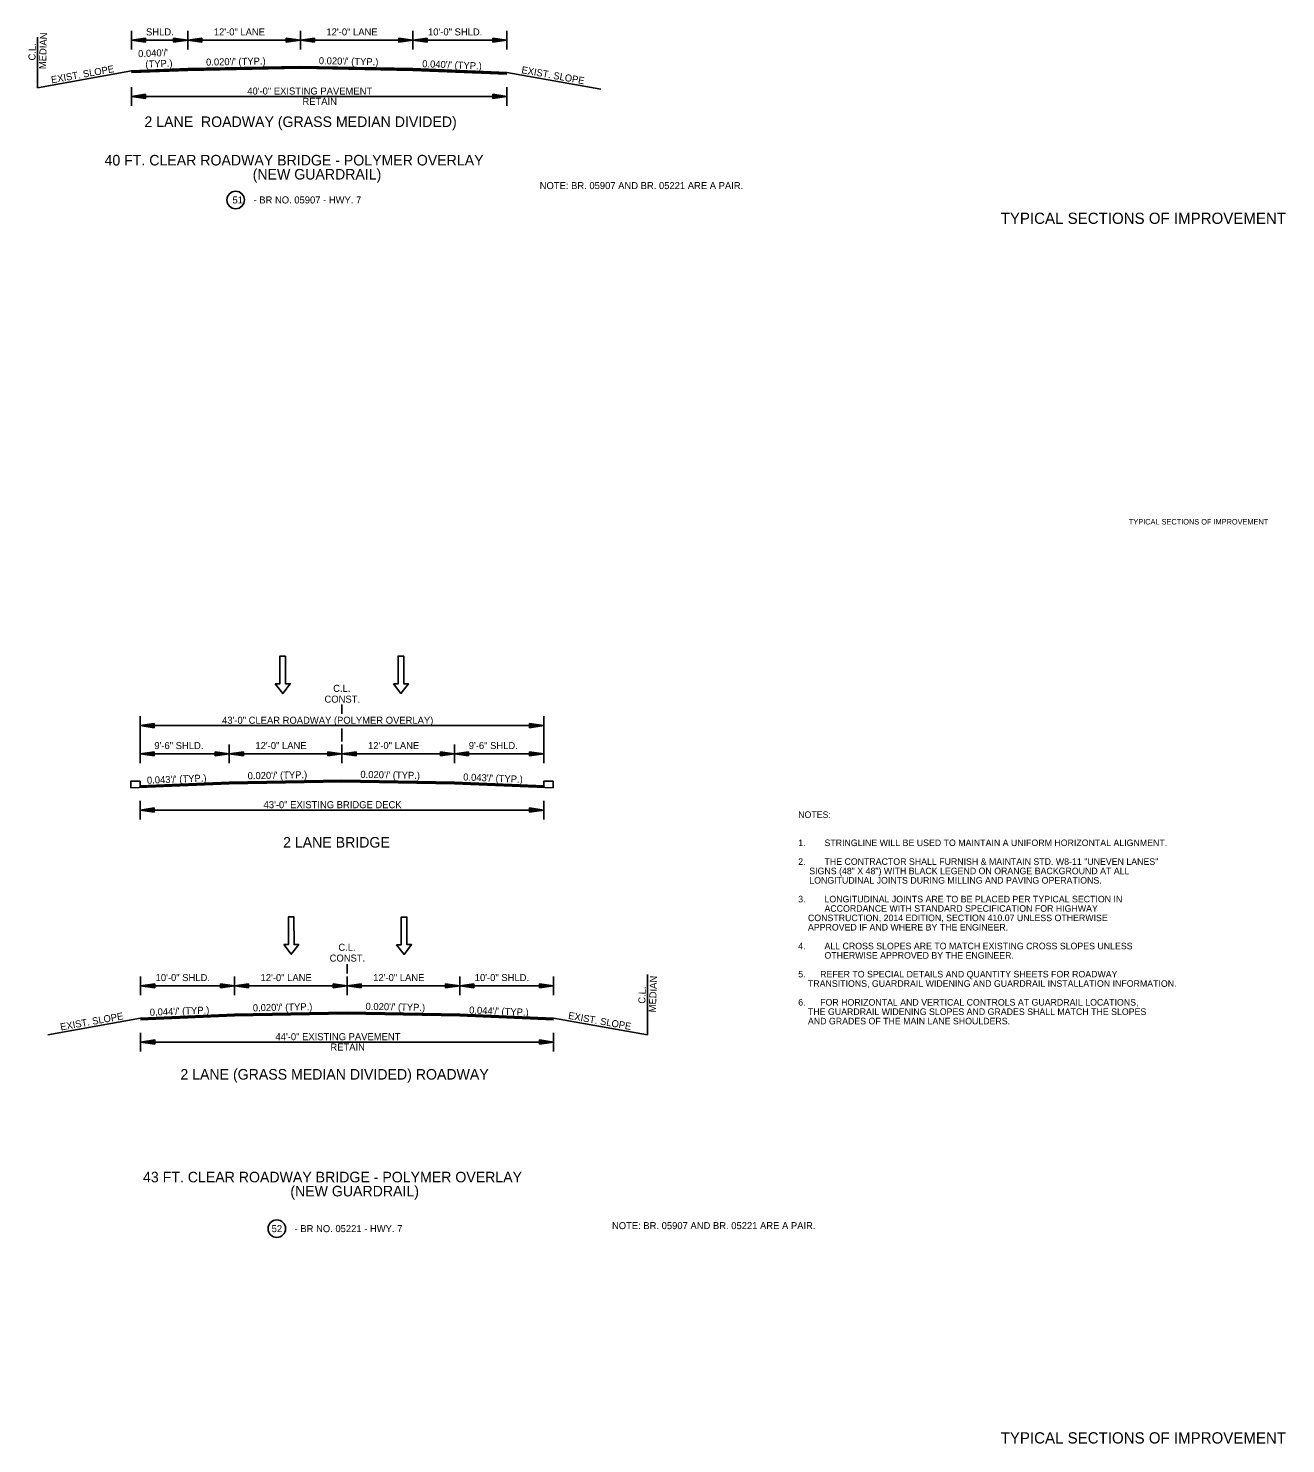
# Model space of a CAD drawing. Extents: x 545241 to 1930787, y -1971772 to 596640.
# Drawn here: x 546928 to 548268, y -1971772 to -1970263 of the extents above; entities that cross this region are included whole.
import ezdxf

# ---------------------------------------------------------------- set-up
doc = ezdxf.new("R2010")
doc.units = 0
for name, color, linetype in [('R_Border', 7, 'Continuous'), ('R_Border Notes', 7, 'Continuous'), ('R_Border Prem', 7, 'Continuous'), ('R_Draft', 7, 'Continuous')]:
    doc.layers.add(name, color=color, linetype=linetype)

# ---------------------------------------------------------------- blocks, each defined once
blk = doc.blocks.new('ARROW')
at = {"layer": 'R_Draft'}
for p, q in [((-2, 0.3), (0, 0)), ((-2, 0.3), (-2, -0.3)), ((-2, 0.25), (-0.334, 0)), ((-2, 0.199), (-0.678, 0)), ((-2, 0.149), (-1.011, 0)), ((-2, 0.097), (-1.35, 0)), ((-2, 0.047), (-1.684, 0)), ((-2, -0.3), (0, 0)), ((-2, -0.098), (-1.35, 0)), ((-2, -0.199), (-0.678, 0)), ((-2, -0.25), (-0.334, 0)), ((-2, -0.149), (-1.011, 0)), ((-2, -0.047), (-1.684, 0))]:
    blk.add_line(p, q, dxfattribs=at)
blk = doc.blocks.new('BPPOLY')
at = {"layer": 'R_Border'}
blk.add_circle((0, 0), 9.34, dxfattribs=at)

msp = doc.modelspace()

# ---------------------------------------------------------------- linework, layer by layer
at = {"layer": 'R_Border'}
for p, q in [((547038.1, -1970265.7), (547038.1, -1970285.7)), ((547098.1, -1970265.7), (547098.1, -1970285.7)), ((547218.1, -1970265.7), (547218.1, -1970285.7)), ((547338.1, -1970265.7), (547338.1, -1970285.7)), ((547438.1, -1970265.7), (547438.1, -1970285.7)), ((546938.2, -1970272.4), (546938.2, -1970326.7)), ((547038.1, -1970275.7), (547438.1, -1970275.7)), ((547038.1, -1970308.5), (546938.2, -1970326.7)), ((547438.1, -1970310.1), (547538.1, -1970328.1)), ((547038.1, -1970325.7), (547038.1, -1970345.7)), ((547438.1, -1970325.7), (547438.1, -1970345.7)), ((547038.1, -1970335.7), (547438.1, -1970335.7)), ((547262.4, -1970983.9), (547262.4, -1970993.9)), ((547047.4, -1970996.4), (547047.4, -1971046.4)), ((547047.4, -1971006.4), (547477.4, -1971006.4)), ((547262.4, -1971009.4), (547262.4, -1971023.4)), ((547477.4, -1970996.4), (547477.4, -1971046.4)), ((547047.4, -1971036.4), (547477.4, -1971036.4)), ((547142.4, -1971026.4), (547142.4, -1971046.4)), ((547262.4, -1971026.4), (547262.4, -1971046.4)), ((547382.4, -1971026.4), (547382.4, -1971046.4)), ((547047.4, -1971086.4), (547047.4, -1971106.4)), ((547047.4, -1971096.4), (547477.4, -1971096.4)), ((547477.4, -1971086.4), (547477.4, -1971106.4)), ((547267.9, -1971260.7), (547267.9, -1971270.7)), ((547047.9, -1971273.7), (547047.9, -1971293.7)), ((547147.9, -1971273.7), (547147.9, -1971293.7)), ((547267.9, -1971273.7), (547267.9, -1971293.7)), ((547387.9, -1971273.7), (547387.9, -1971293.7)), ((547487.9, -1971273.7), (547487.9, -1971293.7)), ((547587.9, -1971271.8), (547587.9, -1971336.1)), ((547047.9, -1971283.7), (547487.9, -1971283.7)), ((547047.9, -1971318.1), (546949.2, -1971336.1)), ((547487.9, -1971318.1), (547587.9, -1971336.1)), ((547047.9, -1971333.7), (547047.9, -1971353.7)), ((547487.9, -1971333.7), (547487.9, -1971353.7)), ((547047.9, -1971343.7), (547487.9, -1971343.7))]:
    msp.add_line(p, q, dxfattribs=at)
for points in [[(547038.1, -1970308.5), (547098.1, -1970306.1), (547218.1, -1970303.7), (547338.1, -1970306.1), (547438.1, -1970310.1)], [(547038.1, -1970308.8), (547098.1, -1970306.4), (547218.1, -1970304), (547338.1, -1970306.4), (547438.1, -1970310.4)], [(547038.1, -1970309.1), (547098.1, -1970306.7), (547218.1, -1970304.3), (547338.1, -1970306.7), (547438.1, -1970310.7)], [(547038.1, -1970309.4), (547098.1, -1970307), (547218.1, -1970304.6), (547338.1, -1970307), (547438.1, -1970311)], [(547038.1, -1970309.7), (547098.1, -1970307.3), (547218.1, -1970304.9), (547338.1, -1970307.3), (547438.1, -1970311.3)], [(547038.1, -1970310), (547098.1, -1970307.6), (547218.1, -1970305.2), (547338.1, -1970307.6), (547438.1, -1970311.6)], [(547038.1, -1970310.3), (547098.1, -1970307.9), (547218.1, -1970305.5), (547338.1, -1970307.9), (547438.1, -1970311.9)], [(547047.4, -1971072.1), (547047.4, -1971065.6), (547037.4, -1971065.6), (547037.4, -1971072.8)], [(547037.4, -1971072.8), (547142.4, -1971068.6), (547262.4, -1971066.2), (547382.4, -1971068.6), (547487.4, -1971072.8)], [(547047.4, -1971070.6), (547142.4, -1971066.8), (547262.4, -1971064.4), (547382.4, -1971066.8), (547477.4, -1971070.6)], [(547047.4, -1971070.9), (547142.4, -1971067.1), (547262.4, -1971064.7), (547382.4, -1971067.1), (547477.4, -1971070.9)], [(547047.4, -1971071.2), (547142.4, -1971067.4), (547262.4, -1971065), (547382.4, -1971067.4), (547477.4, -1971071.2)], [(547047.4, -1971071.5), (547142.4, -1971067.7), (547262.4, -1971065.3), (547382.4, -1971067.7), (547477.4, -1971071.5)], [(547047.4, -1971071.8), (547142.4, -1971068), (547262.4, -1971065.6), (547382.4, -1971068), (547477.4, -1971071.8)], [(547047.4, -1971072.1), (547142.4, -1971068.3), (547262.4, -1971065.9), (547382.4, -1971068.3), (547477.4, -1971072.1)], [(547477.4, -1971072.1), (547477.4, -1971065.6), (547487.4, -1971065.6), (547487.4, -1971072.8)], [(547047.9, -1971318.1), (547147.9, -1971314.1), (547267.9, -1971311.7), (547387.9, -1971314.1), (547487.9, -1971318.1)], [(547047.9, -1971318.4), (547147.9, -1971314.4), (547267.9, -1971312), (547387.9, -1971314.4), (547487.9, -1971318.4)], [(547047.9, -1971318.7), (547147.9, -1971314.7), (547267.9, -1971312.3), (547387.9, -1971314.7), (547487.9, -1971318.7)], [(547047.9, -1971319), (547147.9, -1971315), (547267.9, -1971312.6), (547387.9, -1971315), (547487.9, -1971319)], [(547047.9, -1971319.3), (547147.9, -1971315.3), (547267.9, -1971312.9), (547387.9, -1971315.3), (547487.9, -1971319.3)], [(547047.9, -1971319.6), (547147.9, -1971315.6), (547267.9, -1971313.2), (547387.9, -1971315.6), (547487.9, -1971319.6)], [(547047.9, -1971319.9), (547147.9, -1971315.9), (547267.9, -1971313.5), (547387.9, -1971315.9), (547487.9, -1971319.9)]]:
    msp.add_lwpolyline(points, dxfattribs=at)
for points in [[(547191.3, -1970961.9), (547199.3, -1970972.2), (547207.3, -1970961.8), (547202.3, -1970961.8), (547202.2, -1970932.4), (547196.2, -1970932.4), (547196.3, -1970961.8)], [(547317.3, -1970961.7), (547325.3, -1970972.1), (547333.3, -1970961.7), (547328.3, -1970961.7), (547328.3, -1970932.3), (547322.3, -1970932.3), (547322.3, -1970961.7)], [(547200.4, -1971239.7), (547208.4, -1971250.1), (547216.4, -1971239.7), (547211.4, -1971239.7), (547211.3, -1971210.2), (547205.3, -1971210.3), (547205.4, -1971239.7)], [(547320.6, -1971239.9), (547328.6, -1971250.2), (547336.6, -1971239.8), (547331.6, -1971239.8), (547331.6, -1971210.4), (547325.6, -1971210.4), (547325.6, -1971239.9)]]:
    msp.add_lwpolyline(points, close=True, dxfattribs=at)

# ---------------------------------------------------------------- block references
at = {"layer": 'R_Border', "xscale": 7.5, "yscale": 7.5, "rotation": 180}
for p in [(547038.1, -1970275.7), (547098.1, -1970275.7), (547218.1, -1970275.7), (547338.1, -1970275.7), (547038.1, -1970335.7), (547047.4, -1971006.4), (547047.4, -1971036.4), (547142.4, -1971036.4), (547262.4, -1971036.4), (547382.4, -1971036.4), (547047.4, -1971096.4), (547047.9, -1971283.7), (547147.9, -1971283.7), (547267.9, -1971283.7), (547387.9, -1971283.7), (547047.9, -1971343.7)]:
    msp.add_blockref('ARROW', p, dxfattribs=at)
at = {"layer": 'R_Border', "xscale": 7.5, "yscale": 7.5}
for p in [(547098.1, -1970275.7), (547218.1, -1970275.7), (547338.1, -1970275.7), (547438.1, -1970275.7), (547438.1, -1970335.7), (547477.4, -1971006.4), (547142.4, -1971036.4), (547262.4, -1971036.4), (547382.4, -1971036.4), (547477.4, -1971036.4), (547477.4, -1971096.4), (547147.9, -1971283.7), (547267.9, -1971283.7), (547387.9, -1971283.7), (547487.9, -1971283.7), (547487.9, -1971343.7)]:
    msp.add_blockref('ARROW', p, dxfattribs=at)
at = {"layer": 'R_Border'}
for p in [(547149.2, -1970446.1), (547193, -1971542.6)]:
    msp.add_blockref('BPPOLY', p, dxfattribs=at)

# ---------------------------------------------------------------- texts
for s, height, rotation, p in [('MEDIAN', 7.5, 88.1187, (546947, -1970306.7)), ('C.L.', 7.5, 88.1187, (546935.8, -1970297.5)), ("0.040'/'", 7.5, 2.2916, (547045.4, -1970293.9)), ('(TYP.)', 7.5, 2.2916, (547053.1, -1970305.1)), ("0.020'/' (TYP.)", 7.5, 1.1458, (547117.7, -1970302.9)), ("0.020'/' (TYP.)", 7.5, 358.8542, (547237.7, -1970301.3)), ("0.040'/' (TYP.)", 7.5, 357.7084, (547347.8, -1970304.5)), ('EXIST. SLOPE', 7.5, 10.204, (546953.2, -1970321.8)), ('EXIST. SLOPE', 7.5, 349.796, (547453.2, -1970310.8)), ('TYPICAL SECTIONS OF IMPROVEMENT', 12, 360, (547964.2, -1970471.6)), ("0.020'/' (TYP.)", 7.5, 1.1458, (547162, -1971063.6)), ("0.020'/' (TYP.)", 7.5, 358.8542, (547282, -1971062)), ("0.043'/' (TYP.)", 7.5, 2.2916, (547054.8, -1971068.4)), ("0.043'/' (TYP.)", 7.5, 357.7084, (547391.5, -1971064.8)), ('MEDIAN', 7.5, 88.1187, (547596.8, -1971312.1)), ('C.L.', 7.5, 88.1187, (547585.6, -1971302.9)), ("0.044'/' (TYP.)", 7.5, 2.2916, (547057.8, -1971315.7)), ("0.020'/' (TYP.)", 7.5, 1.1458, (547167.5, -1971310.9)), ("0.020'/' (TYP.)", 7.5, 358.8542, (547287.5, -1971309.3)), ("0.044'/' (TYP.)", 7.5, 357.7084, (547397.8, -1971313.2)), ('EXIST. SLOPE', 7.5, 10.204, (546963, -1971331.4)), ('EXIST. SLOPE', 7.5, 349.796, (547503, -1971318.8)), ('TYPICAL SECTIONS OF IMPROVEMENT', 12, 360, (547964.2, -1971771.6))]:
    msp.add_text(s, height=height, rotation=rotation, dxfattribs=at).set_placement(p)
for s, height, p in [('SHLD.', 7.5, (547053.7, -1970270.7)), ('12\'-0" LANE', 7.5, (547125.9, -1970270.7)), ('12\'-0" LANE', 7.5, (547245.9, -1970270.7)), ('10\'-0" SHLD.', 7.5, (547354.1, -1970270.7)), ('40\'-0" EXISTING PAVEMENT', 7.5, (547161.5, -1970333.7)), ('RETAIN', 7.5, (547220.3, -1970344.7)), ('2 LANE  ROADWAY (GRASS MEDIAN DIVIDED)', 11.25, (547052, -1970368.3)), ('40 FT. CLEAR ROADWAY BRIDGE - POLYMER OVERLAY', 11.25, (547009.5, -1970409.3)), ('(NEW GUARDRAIL)', 11.25, (547167.3, -1970424.3)), ('NOTE: BR. 05907 AND BR. 05221 ARE A PAIR.', 7.5, (547473.1, -1970434.5)), ('51', 7.5, (547145.8, -1970449.8)), ('- BR NO. 05907 - HWY. 7', 7.5, (547168.2, -1970449.8)), ('C.L.', 7.5, (547253, -1970970.4)), ('CONST.', 7.5, (547243.8, -1970981.9)), ('43\'-0" CLEAR ROADWAY (POLYMER OVERLAY)', 7.5, (547134.7, -1971004.4)), ('9\'-6" SHLD.', 7.5, (547062.5, -1971031.4)), ('12\'-0" LANE', 7.5, (547170.2, -1971031.4)), ('12\'-0" LANE', 7.5, (547290.2, -1971031.4)), ('9\'-6" SHLD.', 7.5, (547397.5, -1971031.4)), ('43\'-0" EXISTING BRIDGE DECK', 7.5, (547178.9, -1971094.4)), ('2 LANE BRIDGE', 11.25, (547199.7, -1971136.4)), ('CONST.', 7.5, (547249.3, -1971257.9)), ('C.L.', 7.5, (547258.6, -1971246.4)), ('10\'-0" SHLD.', 7.5, (547063.9, -1971278.7)), ('12\'-0" LANE', 7.5, (547175.7, -1971278.7)), ('12\'-0" LANE', 7.5, (547295.7, -1971278.7)), ('10\'-0" SHLD.', 7.5, (547403.9, -1971278.7)), ('44\'-0" EXISTING PAVEMENT', 7.5, (547191.6, -1971341.7)), ('RETAIN', 7.5, (547250.1, -1971352.7)), ('2 LANE (GRASS MEDIAN DIVIDED) ROADWAY', 11.25, (547090.3, -1971383.7)), ('43 FT. CLEAR ROADWAY BRIDGE - POLYMER OVERLAY', 11.25, (547050.5, -1971493.2)), ('(NEW GUARDRAIL)', 11.25, (547207.4, -1971508.2)), ('NOTE: BR. 05907 AND BR. 05221 ARE A PAIR.', 7.5, (547550.1, -1971543.1)), ('52', 7.5, (547187.5, -1971546.3)), ('- BR NO. 05221 - HWY. 7', 7.5, (547212, -1971546.3))]:
    msp.add_text(s, height=height, dxfattribs=at).set_placement(p)
at = {"layer": 'R_Border Notes'}
for s, p in [('NOTES: ', (547748.5, -1971104.8)), ('1.', (547748.5, -1971134.8)), ('STRINGLINE WILL BE USED TO MAINTAIN A UNIFORM HORIZONTAL ALIGNMENT.', (547776.5, -1971134.8)), ('2.', (547748.5, -1971154.8)), ('    SIGNS (48" X 48") WITH BLACK LEGEND ON ORANGE BACKGROUND AT ALL ', (547749.9, -1971164.8)), ('THE CONTRACTOR SHALL FURNISH & MAINTAIN STD. W8-11 "UNEVEN LANES" ', (547776.5, -1971154.8)), ('    LONGITUDINAL JOINTS DURING MILLING AND PAVING OPERATIONS.', (547749.9, -1971174.8)), ('3.', (547748.5, -1971194.8)), ('LONGITUDINAL JOINTS ARE TO BE PLACED PER TYPICAL SECTION IN ', (547776.5, -1971194.8)), ('ACCORDANCE WITH STANDARD SPECIFICATION FOR HIGHWAY', (547776.5, -1971204.8)), ('    APPROVED IF AND WHERE BY THE ENGINEER.', (547748.5, -1971224.8)), ('    CONSTRUCTION, 2014 EDITION, SECTION 410.07 UNLESS OTHERWISE', (547748.5, -1971214.8)), ('4.', (547748.5, -1971244.8)), ('ALL CROSS SLOPES ARE TO MATCH EXISTING CROSS SLOPES UNLESS ', (547776.5, -1971244.8)), ('OTHERWISE APPROVED BY THE ENGINEER.', (547776.5, -1971254.8)), ('5.      REFER TO SPECIAL DETAILS AND QUANTITY SHEETS FOR ROADWAY', (547748.5, -1971274.8)), ('    TRANSITIONS, GUARDRAIL WIDENING AND GUARDRAIL INSTALLATION INFORMATION.', (547748.5, -1971284.8)), ('6.      FOR HORIZONTAL AND VERTICAL CONTROLS AT GUARDRAIL LOCATIONS,', (547748.5, -1971304.8)), ('    THE GUARDRAIL WIDENING SLOPES AND GRADES SHALL MATCH THE SLOPES', (547748.5, -1971314.8)), ('    AND GRADES OF THE MAIN LANE SHOULDERS. ', (547748.5, -1971324.8))]:
    msp.add_text(s, height=7, dxfattribs=at).set_placement(p)
at = {"layer": 'R_Border Prem'}
msp.add_text('TYPICAL SECTIONS OF IMPROVEMENT', height=5.862, rotation=360, dxfattribs=at).set_placement((548100.8, -1970792))

doc.saveas('drawing.dxf')
